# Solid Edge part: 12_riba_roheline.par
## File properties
Author: Romil
Template: Iso Part.par
Last saved by: Romil
Revision: 14
Application: Solid Edge
Accuracy: 0.990
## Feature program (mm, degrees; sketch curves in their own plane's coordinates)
sketch for "unnamed Protrusion 1" plane through (0, 0, 0) normal (0, 0, 1) x-axis (1, 0, 0)
  line (-55.9, -3.9) -> (39.9, -3.9)
  line (39.9, -3.9) -> (39.9, 3.9)
  line (39.9, 3.9) -> (-55.9, 3.9)
  line (-55.9, 3.9) -> (-55.9, -3.9)
extrude "unnamed Protrusion 1" add finite 9.6 along +normal
sketch for "ExtrudedProtrusion_2" plane through (0, 0, 0) normal (0, 0, 1) x-axis (1, 0, 0)
  circle centre (-52, 0) radius 2.4
extrude "ExtrudedProtrusion_2" add finite 11.4 along +normal
sketch for "ExtrudedCutout_2" plane through (-52, 0, 11.4) normal (0, 0, 1) x-axis (1, 0, 0)
  circle centre (0, 0) radius 1.5
extrude "ExtrudedCutout_2" cut finite 1.8 along -normal
pattern "unnamed Pattern 1" of "ExtrudedCutout_2", "ExtrudedProtrusion_2"
extrude "unnamed Protrusion 2" add finite 11.4
extrude "unnamed Cutout 1" cut finite 1.8
extrude "unnamed Protrusion 3" add finite 11.4
extrude "unnamed Cutout 2" cut finite 1.8
extrude "unnamed Protrusion 4" add finite 11.4
extrude "unnamed Cutout 3" cut finite 1.8
extrude "unnamed Protrusion 5" add finite 11.4
extrude "unnamed Cutout 4" cut finite 1.8
extrude "unnamed Protrusion 6" add finite 11.4
extrude "unnamed Cutout 5" cut finite 1.8
extrude "unnamed Protrusion 7" add finite 11.4
extrude "unnamed Cutout 6" cut finite 1.8
extrude "unnamed Protrusion 8" add finite 11.4
extrude "unnamed Cutout 7" cut finite 1.8
extrude "unnamed Protrusion 9" add finite 11.4
extrude "unnamed Cutout 8" cut finite 1.8
extrude "unnamed Protrusion 10" add finite 11.4
extrude "unnamed Cutout 9" cut finite 1.8
extrude "unnamed Protrusion 11" add finite 11.4
extrude "unnamed Cutout 10" cut finite 1.8
extrude "unnamed Protrusion 12" add finite 11.4
extrude "unnamed Cutout 11" cut finite 1.8
sketch for "ExtrudedCutout_54" plane through (0, 0, 0) normal (0, 0, -1) x-axis (1, 0, 0)
  line (38.4, -2.4) -> (-54.4, -2.4)
  line (-54.4, -2.4) -> (-54.4, 2.4)
  line (-54.4, 2.4) -> (38.4, 2.4)
  line (38.4, 2.4) -> (38.4, -2.4)
extrude "ExtrudedCutout_54" cut finite 8.1 along -normal
sketch for "ExtrudedProtrusion_107" plane through (0, 0, 0) normal (0, 0, -1) x-axis (1, 0, 0)
  circle centre (32, 0) radius 1.5
extrude "ExtrudedProtrusion_107" add finite 3 along -normal
sketch for "unnamed Cutout 12" plane through (48, 0, 0) normal (0, 0, -1) x-axis (1, 0, 0)
  circle centre (-16, 0) radius 1
extrude "unnamed Cutout 12" cut finite 4.2817 along -normal
pattern "unnamed Pattern 2" of "unnamed Cutout 12", "ExtrudedProtrusion_107"
extrude "unnamed Protrusion 13" add finite 3
extrude "unnamed Cutout 13" cut finite 4.2817
extrude "unnamed Protrusion 14" add finite 3
extrude "unnamed Cutout 14" cut finite 4.2817
extrude "unnamed Protrusion 15" add finite 3
extrude "unnamed Cutout 15" cut finite 4.2817
extrude "unnamed Protrusion 16" add finite 3
extrude "unnamed Cutout 16" cut finite 4.2817
extrude "unnamed Protrusion 17" add finite 3
extrude "unnamed Cutout 17" cut finite 4.2817
extrude "unnamed Protrusion 18" add finite 3
extrude "unnamed Cutout 18" cut finite 4.2817
extrude "unnamed Protrusion 19" add finite 3
extrude "unnamed Cutout 19" cut finite 4.2817
extrude "unnamed Protrusion 20" add finite 3
extrude "unnamed Cutout 20" cut finite 4.2817
extrude "unnamed Protrusion 21" add finite 3
extrude "unnamed Cutout 21" cut finite 4.2817
extrude "unnamed Protrusion 22" add finite 3
extrude "unnamed Cutout 22" cut finite 4.2817
sketch for "unnamed Protrusion 23" plane through (0, -3.9, 4.8) normal (0, -1, 0) x-axis (1, 0, 0)
  circle centre (-48, 1) radius 3.8
extrude "unnamed Protrusion 23" add to key point along -normal
sketch for "ExtrudedCutout_68" plane through (0, -3.9, 4.8) normal (0, -1, 0) x-axis (1, 0, 0)
  circle centre (-48, 1) radius 2.4
extrude "ExtrudedCutout_68" cut finite 44.876 along -normal
sketch for "ExtrudedCutout_69" plane through (0, -3.9, 4.8) normal (0, -1, 0) x-axis (1, 0, 0)
  circle centre (-48, 1) radius 3.1
extrude "ExtrudedCutout_69" cut finite 0.9 along -normal
mirror "unnamed Mirror 1" of "ExtrudedCutout_69" about plane through (0, 0, 0) normal (0, -1, 0)
extrude "unnamed Cutout 23" cut finite 0.9
pattern "unnamed Pattern 3" of "unnamed Protrusion 23", "ExtrudedCutout_69", "ExtrudedCutout_68", "unnamed Mirror 1"
extrude "unnamed Protrusion 24" add finite 7.8
extrude "unnamed Cutout 24" cut finite 44.876
extrude "unnamed Cutout 25" cut finite 0.9
extrude "unnamed Cutout 26" cut finite 0.9
extrude "unnamed Protrusion 25" add finite 7.8
extrude "unnamed Cutout 27" cut finite 44.876
extrude "unnamed Cutout 28" cut finite 0.9
extrude "unnamed Cutout 29" cut finite 0.9
extrude "unnamed Protrusion 26" add finite 7.8
extrude "unnamed Cutout 30" cut finite 44.876
extrude "unnamed Cutout 31" cut finite 0.9
extrude "unnamed Cutout 32" cut finite 0.9
extrude "unnamed Protrusion 27" add finite 7.8
extrude "unnamed Cutout 33" cut finite 44.876
extrude "unnamed Cutout 34" cut finite 0.9
extrude "unnamed Cutout 35" cut finite 0.9
extrude "unnamed Protrusion 28" add finite 7.8
extrude "unnamed Cutout 36" cut finite 44.876
extrude "unnamed Cutout 37" cut finite 0.9
extrude "unnamed Cutout 38" cut finite 0.9
extrude "unnamed Protrusion 29" add finite 7.8
extrude "unnamed Cutout 39" cut finite 44.876
extrude "unnamed Cutout 40" cut finite 0.9
extrude "unnamed Cutout 41" cut finite 0.9
extrude "unnamed Protrusion 30" add finite 7.8
extrude "unnamed Cutout 42" cut finite 44.876
extrude "unnamed Cutout 43" cut finite 0.9
extrude "unnamed Cutout 44" cut finite 0.9
extrude "unnamed Protrusion 31" add finite 7.8
extrude "unnamed Cutout 45" cut finite 44.876
extrude "unnamed Cutout 46" cut finite 0.9
extrude "unnamed Cutout 47" cut finite 0.9
extrude "unnamed Protrusion 32" add finite 7.8
extrude "unnamed Cutout 48" cut finite 44.876
extrude "unnamed Cutout 49" cut finite 0.9
extrude "unnamed Cutout 50" cut finite 0.9
extrude "unnamed Protrusion 33" add finite 7.8
extrude "unnamed Cutout 51" cut finite 44.876
extrude "unnamed Cutout 52" cut finite 0.9
extrude "unnamed Cutout 53" cut finite 0.9
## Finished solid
Body 1: solid body, 180 faces, 248 edges, 60 vertices.
  Faces by surface: cylinder 101, plane 79
  Edges by curve: circle 158, line 68, intersection 22
Bounding box of the edges (mm): 95.800 x 7.800 x 11.400, from (-55.9, -3.9, 0) to (39.9, 3.9, 11.4).
Cylindrical faces by radius (mm): R1 x11, R1.5 x23, R2.4 x23, R3.1 x22, R3.8 x22
Planar faces by outward normal: +x 2, +y 13, +z 25, -x 2, -y 13, -z 24
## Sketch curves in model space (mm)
line (38.4, -2.4, 0) -> (38.4, 2.4, 0)
line (38.4, 2.4, 0) -> (-54.4, 2.4, 0)
line (-54.4, 2.4, 0) -> (-54.4, -2.4, 0)
line (-54.4, -2.4, 0) -> (38.4, -2.4, 0)
circle centre (-48, -3.9, 5.8) radius 3.8
circle centre (-48, -3.9, 5.8) radius 3.1
circle centre (-48, -3.9, 5.8) radius 2.4
circle centre (-52, 0, 0) radius 2.4
line (-55.9, 24.9381, 0) -> (-55.9, -18.0275, 0)
line (39.9, -3.9, 0) -> (39.9, 3.9, 0)
line (39.9, 3.9, 0) -> (-55.9, 3.9, 0)
line (-55.9, 3.9, 0) -> (-55.9, -3.9, 0)
line (-55.9, -3.9, 0) -> (39.9, -3.9, 0)
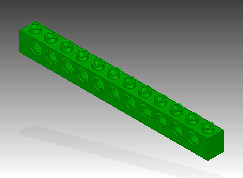
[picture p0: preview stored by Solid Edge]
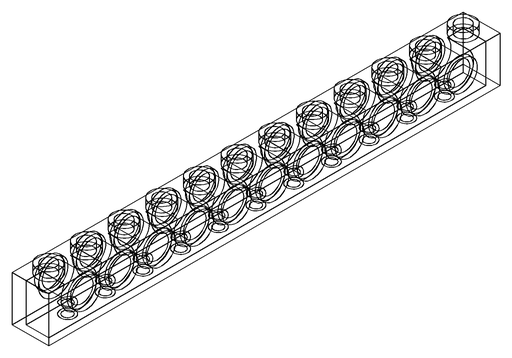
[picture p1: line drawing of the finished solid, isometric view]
